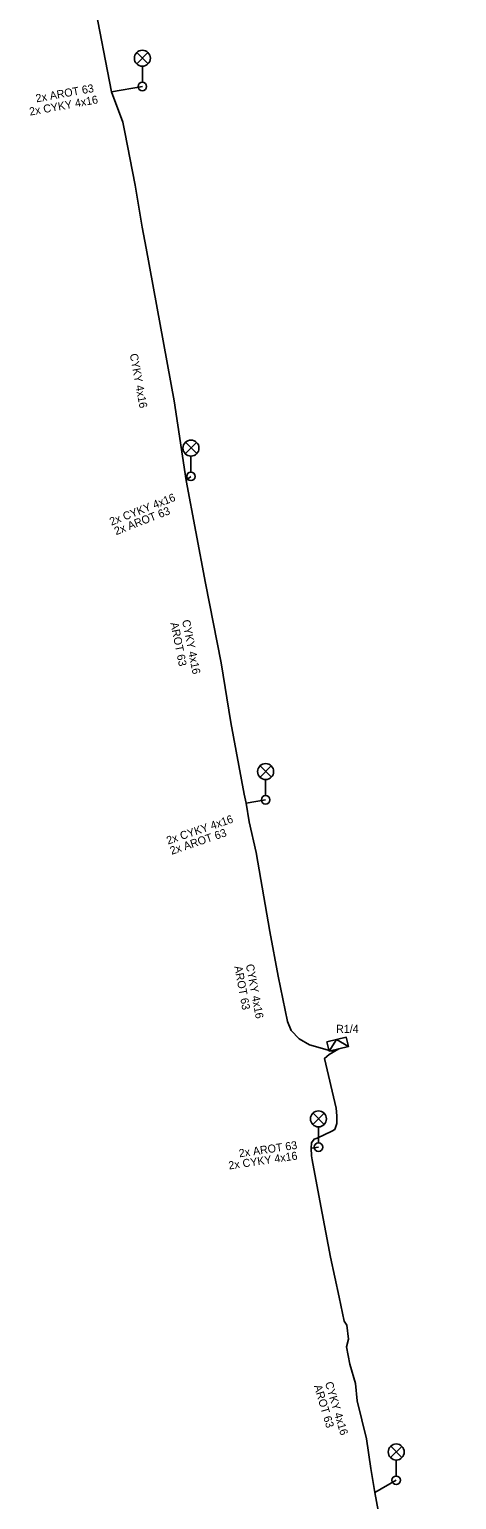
# Model space of a CAD drawing. Extents: x -641884 to -641258, y -1196509 to -1195931.
# Drawn here: x -641798.1 to -641758.1, y -1196363.4 to -1196225.6 of the extents above; entities that cross this region are included whole.
import ezdxf

# ---------------------------------------------------------------- set-up
doc = ezdxf.new("R2010")
doc.units = 0
for name, color, linetype in [('CIZÍ_NADZEM', 7, 'Continuous'), ('CIZÍ_NADZEM_POPIS', 7, 'Continuous'), ('TECH_OCHR_PÁSMO_HRAN', 7, 'Continuous'), ('Vrstva 22', 7, 'Continuous'), ('Vrstva 31', 7, 'Continuous'), ('ZP_EON', 7, 'Continuous'), ('ZP_EON_POPIS', 7, 'Continuous')]:
    doc.layers.add(name, color=color, linetype=linetype)

msp = doc.modelspace()

# ---------------------------------------------------------------- linework, layer by layer
at = {"layer": 'CIZÍ_NADZEM'}
msp.add_lwpolyline([(-641770.24, -1196320.46), (-641768.41, -1196320.03), (-641768.21, -1196320.91), (-641770.03, -1196321.33)], close=True, dxfattribs=at)
msp.add_lwpolyline([(-641770.03, -1196321.33), (-641769.32, -1196320.24), (-641768.21, -1196320.91)], dxfattribs=at)
at = {"layer": 'TECH_OCHR_PÁSMO_HRAN'}
for p, q in [((-641787.53, -1196230.94), (-641790.42, -1196231.44)), ((-641783.41, -1196267.86), (-641782.97, -1196267.47)), ((-641777.8, -1196298.09), (-641775.97, -1196297.79)), ((-641771.02, -1196330.33), (-641771.7, -1196330.43)), ((-641765.75, -1196362.71), (-641763.73, -1196361.55))]:
    msp.add_line(p, q, dxfattribs=at)
for points in [[(-641795.57, -1196200.51), (-641795.14, -1196202.56), (-641795.9, -1196203.65), (-641795.08, -1196208.11), (-641794.86, -1196209.45), (-641794.67, -1196210.46), (-641793.14, -1196216.85), (-641792.05, -1196223.04), (-641790.98, -1196228.54), (-641790.42, -1196231.44)], [(-641790.42, -1196231.44), (-641789.35, -1196234.29), (-641789.18, -1196235.22), (-641788.19, -1196240.19), (-641787.56, -1196244.11), (-641787.16, -1196246.08), (-641784.54, -1196260.4), (-641783.41, -1196267.86)], [(-641783.41, -1196267.86), (-641781.62, -1196277.48), (-641780.14, -1196284.95), (-641779.23, -1196290.55), (-641777.98, -1196297.24), (-641777.8, -1196298.09)], [(-641777.8, -1196298.09), (-641777.52, -1196299.84), (-641776.87, -1196302.73), (-641775.59, -1196310.11), (-641774.81, -1196314.31), (-641773.93, -1196318.55), (-641773.57, -1196319.41), (-641772.82, -1196320.18), (-641771.85, -1196320.75), (-641769.76, -1196321.35), (-641769.12, -1196321.12)], [(-641769.12, -1196321.12), (-641770.01, -1196321.65), (-641770.44, -1196322.02), (-641769.37, -1196326.67), (-641769.29, -1196327.41), (-641769.3, -1196328.11), (-641769.49, -1196328.67), (-641769.77, -1196328.84), (-641771.14, -1196329.48), (-641771.43, -1196329.59), (-641771.66, -1196329.94), (-641771.7, -1196330.43)], [(-641771.7, -1196330.43), (-641771.67, -1196331.15), (-641771.62, -1196331.51), (-641770.9, -1196335.36), (-641769.89, -1196340.64), (-641769.07, -1196344.38), (-641768.6, -1196346.64), (-641768.36, -1196347.03), (-641768.2, -1196348.34), (-641768.4, -1196349.05), (-641768.08, -1196350.68), (-641767.54, -1196352.49), (-641767.39, -1196354.12), (-641766.53, -1196357.67), (-641766.12, -1196360.44), (-641765.75, -1196362.71)], [(-641765.75, -1196362.71), (-641765.11, -1196366.08), (-641764.84, -1196367.88), (-641764.71, -1196368.37), (-641764.18, -1196371.1), (-641763.43, -1196375.14), (-641762.88, -1196377.68), (-641761.95, -1196380.43), (-641760.43, -1196383.74), (-641759.08, -1196389.25), (-641758.07, -1196393.53)]]:
    msp.add_lwpolyline(points, dxfattribs=at)
at = {"layer": 'Vrstva 31'}
for p, q in [((-641788.06, -1196228.82), (-641787, -1196227.76)), ((-641786.99, -1196228.81), (-641788.04, -1196227.75)), ((-641787.53, -1196229.04), (-641787.53, -1196230.54)), ((-641782.43, -1196265.34), (-641783.48, -1196264.28)), ((-641783.5, -1196265.35), (-641782.44, -1196264.29)), ((-641782.97, -1196265.57), (-641782.97, -1196267.07)), ((-641776.5, -1196295.67), (-641775.44, -1196294.61)), ((-641775.43, -1196295.66), (-641776.48, -1196294.6)), ((-641775.97, -1196295.89), (-641775.97, -1196297.39)), ((-641771.55, -1196328.21), (-641770.49, -1196327.15)), ((-641770.48, -1196328.2), (-641771.53, -1196327.14)), ((-641771.02, -1196328.43), (-641771.02, -1196329.93)), ((-641764.26, -1196359.43), (-641763.2, -1196358.37)), ((-641763.19, -1196359.42), (-641764.24, -1196358.36)), ((-641763.73, -1196359.65), (-641763.73, -1196361.15))]:
    msp.add_line(p, q, dxfattribs=at)
for centre, radius in [((-641787.53, -1196228.29), 0.75), ((-641787.53, -1196230.94), 0.4), ((-641782.97, -1196264.82), 0.75), ((-641782.97, -1196267.47), 0.4), ((-641775.97, -1196295.14), 0.75), ((-641775.97, -1196297.79), 0.4), ((-641771.02, -1196327.68), 0.75), ((-641771.02, -1196330.33), 0.4), ((-641763.73, -1196358.9), 0.75), ((-641763.73, -1196361.55), 0.4)]:
    msp.add_circle(centre, radius, dxfattribs=at)
at = {"layer": 'ZP_EON'}
for p, q in [((-641787.53, -1196230.94), (-641790.42, -1196231.44)), ((-641783.41, -1196267.86), (-641782.97, -1196267.47)), ((-641777.8, -1196298.09), (-641775.97, -1196297.79)), ((-641771.02, -1196330.33), (-641771.7, -1196330.43)), ((-641765.75, -1196362.71), (-641763.73, -1196361.55))]:
    msp.add_line(p, q, dxfattribs=at)
for points in [[(-641795.57, -1196200.51), (-641795.14, -1196202.56), (-641795.9, -1196203.65), (-641795.08, -1196208.11), (-641794.86, -1196209.45), (-641794.67, -1196210.46), (-641793.14, -1196216.85), (-641792.05, -1196223.04), (-641790.98, -1196228.54), (-641790.42, -1196231.44)], [(-641790.42, -1196231.44), (-641789.35, -1196234.29), (-641789.18, -1196235.22), (-641788.19, -1196240.19), (-641787.56, -1196244.11), (-641787.16, -1196246.08), (-641784.54, -1196260.4), (-641783.41, -1196267.86)], [(-641783.41, -1196267.86), (-641781.62, -1196277.48), (-641780.14, -1196284.95), (-641779.23, -1196290.55), (-641777.98, -1196297.24), (-641777.8, -1196298.09)], [(-641777.8, -1196298.09), (-641777.52, -1196299.84), (-641776.87, -1196302.73), (-641775.59, -1196310.11), (-641774.81, -1196314.31), (-641773.93, -1196318.55), (-641773.57, -1196319.41), (-641772.82, -1196320.18), (-641771.85, -1196320.75), (-641769.76, -1196321.35), (-641769.12, -1196321.12)], [(-641769.12, -1196321.12), (-641770.01, -1196321.65), (-641770.44, -1196322.02), (-641769.37, -1196326.67), (-641769.29, -1196327.41), (-641769.3, -1196328.11), (-641769.49, -1196328.67), (-641769.77, -1196328.84)], [(-641769.77, -1196328.84), (-641771.14, -1196329.48), (-641771.43, -1196329.59), (-641771.66, -1196329.94), (-641771.7, -1196330.43)], [(-641771.7, -1196330.43), (-641771.67, -1196331.15), (-641771.62, -1196331.51), (-641770.9, -1196335.36), (-641769.89, -1196340.64), (-641769.07, -1196344.38), (-641768.6, -1196346.64), (-641768.36, -1196347.03), (-641768.2, -1196348.34), (-641768.4, -1196349.05), (-641768.08, -1196350.68), (-641767.54, -1196352.49), (-641767.39, -1196354.12), (-641766.53, -1196357.67), (-641766.12, -1196360.44), (-641765.75, -1196362.71)], [(-641765.75, -1196362.71), (-641765.11, -1196366.08), (-641764.84, -1196367.88), (-641764.71, -1196368.37), (-641764.18, -1196371.1), (-641763.43, -1196375.14), (-641762.88, -1196377.68), (-641761.95, -1196380.43), (-641760.43, -1196383.74), (-641759.08, -1196389.25), (-641758.07, -1196393.53)]]:
    msp.add_lwpolyline(points, dxfattribs=at)

# ---------------------------------------------------------------- texts
at = {"layer": 'CIZÍ_NADZEM_POPIS'}
msp.add_text('R1/4', height=0.75, dxfattribs=at).set_placement((-641769.37, -1196319.62))
at = {"layer": 'Vrstva 22'}
for s, rotation, p in [('2x AROT 63', 10.3048, (-641797.46, -1196232.43)), ('2x AROT 63', 21.2974, (-641789.99, -1196272.99)), ('AROT 63', 281.2066, (-641784.9, -1196281.22)), ('2x AROT 63', 18.7258, (-641784.79, -1196302.94)), ('AROT 63', 280.5208, (-641778.91, -1196313.41)), ('2x AROT 63', 8.3659, (-641778.43, -1196331.29)), ('AROT 63', 286.6121, (-641771.45, -1196352.71))]:
    msp.add_text(s, height=0.75, rotation=rotation, dxfattribs=at).set_placement(p)
at = {"layer": 'ZP_EON_POPIS'}
for s, rotation, p in [('2x CYKY 4x16', 10.3048, (-641798.06, -1196233.67)), ('CYKY 4x16', 280.3682, (-641788.71, -1196256.03)), ('2x CYKY 4x16', 21.2974, (-641790.43, -1196272.1)), ('CYKY 4x16', 281.2066, (-641783.81, -1196280.98)), ('2x CYKY 4x16', 18.7258, (-641785.12, -1196301.98)), ('CYKY 4x16', 280.5208, (-641777.83, -1196313.24)), ('2x CYKY 4x16', 8.3659, (-641779.4, -1196332.43)), ('CYKY 4x16', 286.6121, (-641770.42, -1196352.43))]:
    msp.add_text(s, height=0.75, rotation=rotation, dxfattribs=at).set_placement(p)

doc.saveas('drawing.dxf')
